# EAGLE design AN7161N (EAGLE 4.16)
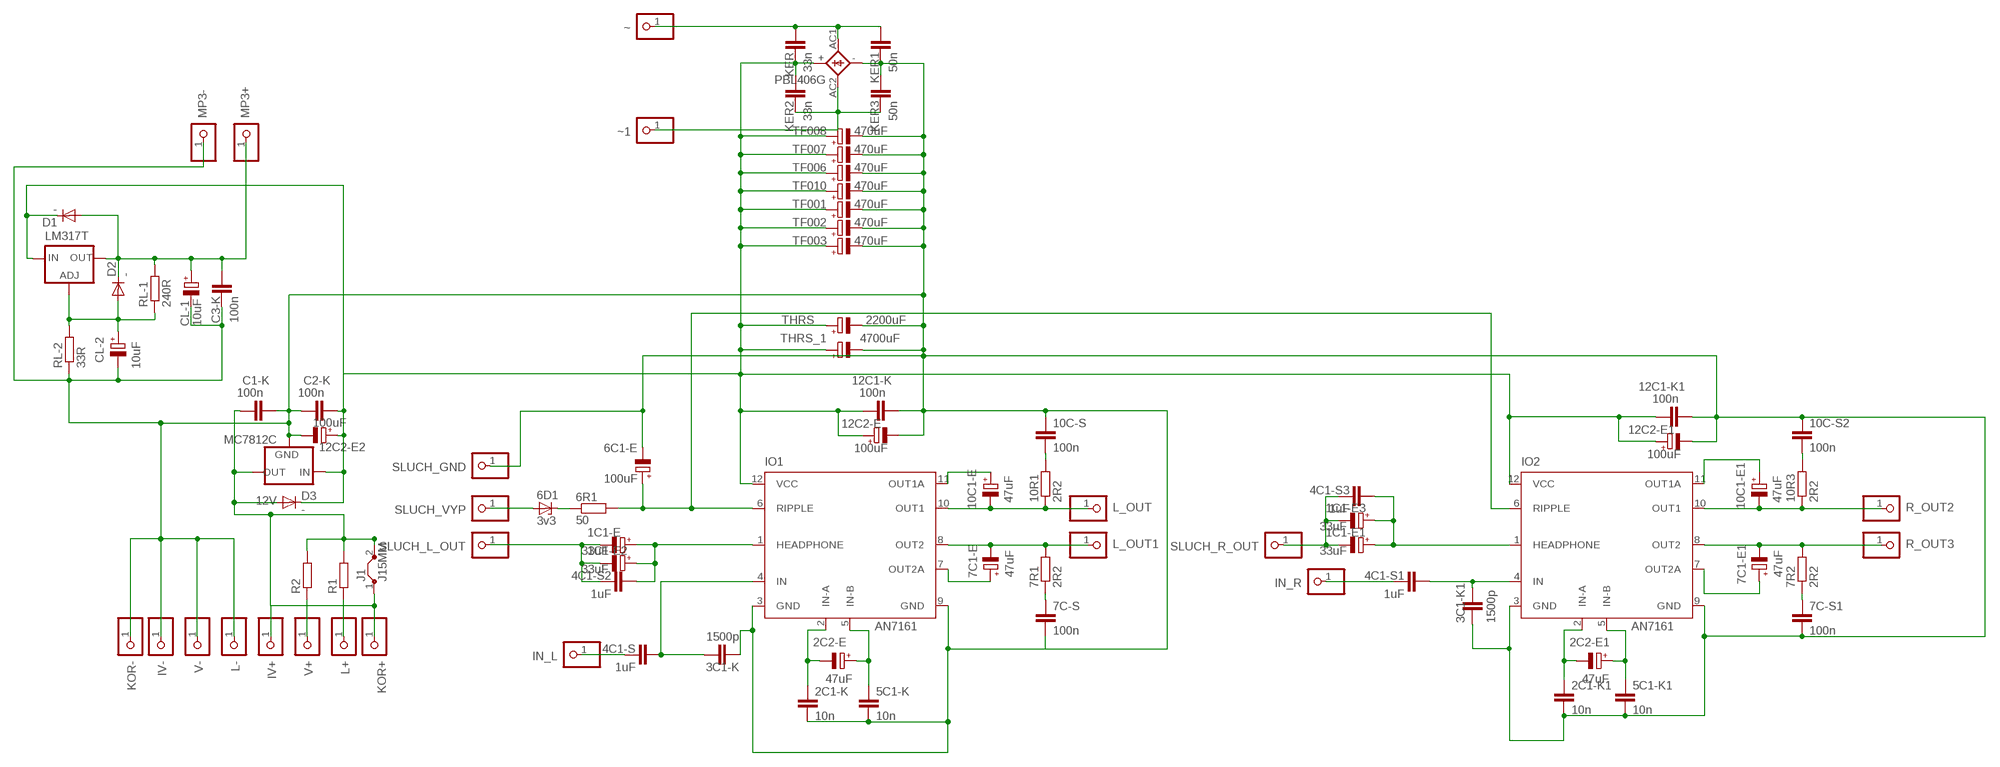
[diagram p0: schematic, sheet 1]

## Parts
1C1-E  33uF  CPOL-EUE5-6  [E5-6]
1C1-E1  33uF  CPOL-EUE5-6  [E5-6]
1C1-E2  33uF  CPOL-EUE5-6  [E5-6]
1C1-E3  33uF  CPOL-EUE5-6  [E5-6]
2C1-K  10n  C-EU050-024X044  [C050-024X044]
2C1-K1  10n  C-EU050-024X044  [C050-024X044]
2C2-E  47uF  CPOL-EUE5-6  [E5-6]
2C2-E1  47uF  CPOL-EUE5-6  [E5-6]
3C1-K  1500p  C-EU102-043X133  [C102-043X133]
3C1-K1  1500p  C-EU102-043X133  [C102-043X133]
4C1-S  1uF  C-EU225-087X268  [C225-087X268]
4C1-S1  1uF  C-EU225-087X268  [C225-087X268]
4C1-S2  1uF  C-EU225-087X268  [C225-087X268]
4C1-S3  1uF  C-EU225-087X268  [C225-087X268]
5C1-K  10n  C-EU050-024X044  [C050-024X044]
5C1-K1  10n  C-EU050-024X044  [C050-024X044]
6C1-E  100uF  CPOL-EUE5-10.5  [E5-10,5]
6D1  3v3  1N821  [DO35Z10]
6R1  50  R-EU_0207/12  [0207/12]
7C1-E  47uF  CPOL-EUE5-6  [E5-6]
7C1-E1  47uF  CPOL-EUE5-6  [E5-6]
7C-S  100n  CXXC15B8  [XC15B8]
7C-S1  100n  CXXC15B8  [XC15B8]
7R1  2R2  R-EU_0207/15  [0207/15]
7R2  2R2  R-EU_0207/15  [0207/15]
10C1-E  47uF  CPOL-EUE5-6  [E5-6]
10C1-E1  47uF  CPOL-EUE5-6  [E5-6]
10C-S  100n  CXXC15B8  [XC15B8]
10C-S2  100n  CXXC15B8  [XC15B8]
10R1  2R2  R-EU_0207/15  [0207/15]
10R3  2R2  R-EU_0207/15  [0207/15]
12C1-K  100n  C-EU050-024X044  [C050-024X044]
12C1-K1  100n  C-EU050-024X044  [C050-024X044]
12C2-E  100uF  CPOL-EUE5-8.5  [E5-8,5]
12C2-E1  100uF  CPOL-EUE5-8.5  [E5-8,5]
12C2-E2  100uF  CPOL-EUE5-8.5  [E5-8,5]
C1-K  100n  C-EU050-024X044  [C050-024X044]
C2-K  100n  C-EU050-024X044  [C050-024X044]
C3-K  100n  C-EU050-024X044  [C050-024X044]
CL-1  10uF  CPOL-EUE5-6  [E5-6]
CL-2  10uF  CPOL-EUE5-6  [E5-6]
D1  -  1N5060GP  [DO15-12]
D2  -  1N5060GP  [DO15-12]
D3  -  1N5060GP  [DO15-12]
IN_L  PINHD-1X1  [1X01]
IN_R  PINHD-1X1  [1X01]
IO1  AN7161  [SIP-12]
IO2  AN7161  [SIP-12]
IV+  PINHD-1X1  [1X01]
IV-  PINHD-1X1  [1X01]
J1  J15MM  [15]
KER  33n  C-EU050-024X044  [C050-024X044]
KER1  50n  C-EU050-024X044  [C050-024X044]
KER2  33n  C-EU050-024X044  [C050-024X044]
KER3  50n  C-EU050-024X044  [C050-024X044]
KOR+  PINHD-1X1  [1X01]
KOR-  PINHD-1X1  [1X01]
L+  PINHD-1X1  [1X01]
L-  PINHD-1X1  [1X01]
L_OUT  PINHD-1X1  [1X01]
L_OUT1  PINHD-1X1  [1X01]
LM317T  LM317TS  [317TS]
MC7812C  12V  78XXS  [78XXS]
MP3+  PINHD-1X1  [1X01]
MP3-  PINHD-1X1  [1X01]
PBL406G  KBL  [KBL]
R1  R-EU_0411/15  [0411/15]
R2  R-EU_0411/15  [0411/15]
R_OUT2  PINHD-1X1  [1X01]
R_OUT3  PINHD-1X1  [1X01]
RL-1  240R  R-EU_0207/12  [0207/12]
RL-2  33R  R-EU_0207/12  [0207/12]
SLUCH_GND  PINHD-1X1  [1X01]
SLUCH_L_OUT  PINHD-1X1  [1X01]
SLUCH_R_OUT  PINHD-1X1  [1X01]
SLUCH_VYP  PINHD-1X1  [1X01]
TF001  470uF  CPOL-EUE35-12AXIAL  [E35-12]
TF002  470uF  CPOL-EUE35-12AXIAL  [E35-12]
TF003  470uF  CPOL-EUE35-12AXIAL  [E35-12]
TF006  470uF  CPOL-EUE35-12AXIAL  [E35-12]
TF007  470uF  CPOL-EUE35-12AXIAL  [E35-12]
TF008  470uF  CPOL-EUE35-12AXIAL  [E35-12]
TF010  470uF  CPOL-EUE35-12AXIAL  [E35-12]
THRS  2200uF  CPOL-EUE7.5-18  [E7,5-18]
THRS_1  4700uF  CPOL-EUE7.5-18  [E7,5-18]
V+  PINHD-1X1  [1X01]
V-  PINHD-1X1  [1X01]
~  PINHD-1X1  [1X01]
~1  PINHD-1X1  [1X01]

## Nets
N$1: 2C1-K1.1 2C2-E1.- IO2.2(IN-A)
N$2: 1C1-E2.- 1C1-E.- 4C1-S2.1 SLUCH_L_OUT.1
N$4: 6D1.C 6R1.1
N$6: 2C1-K.1 2C2-E.- IO1.2(IN-A)
N$8: 4C1-S.1 IN_L.1
N$9: 10C1-E1.+ IO2.11(OUT1A)
N$11: 2C2-E.+ 5C1-K.1 IO1.5(IN-B)
N$12: 10C1-E.+ IO1.11(OUT1A)
N$14: 7C1-E.- 7R1.2 IO1.8(OUT2) L_OUT1.1
N$15: 7C1-E.+ IO1.7(OUT2A)
N$16: 7C-S.1 7R1.1
N$17: 10C-S.2 10R1.2
N$18: 7C1-E1.- 7R2.2 IO2.8(OUT2) R_OUT3.1
N$21: 7C-S1.1 7R2.1
N$23: 1C1-E1.- 1C1-E3.- 4C1-S3.1 SLUCH_R_OUT.1
N$27: 1C1-E2.+ 1C1-E.+ 4C1-S2.2 IO1.1(HEADPHONE)
N$28: 2C2-E1.+ 5C1-K1.1 IO2.5(IN-B)
N$30: 10C-S2.2 10R3.2
N$32: 7C1-E1.+ IO2.7(OUT2A)
N$33: KER1.2 KER.2 PBL406G.AC1(AC2) ~.1
N$34: C1-K.1 D3.A IV+.1 J1.1 J1.2 KOR+.1 MC7812C.OUT R1.2 R2.2
N$35: L+.1 R1.1
N$38: 3C1-K1.1 4C1-S1.2 IO2.4(IN)
N$41: 4C1-S1.1 IN_R.1
N$42: 10C1-E1.- 10R3.1 IO2.10(OUT1) R_OUT2.1
N$46: 1C1-E1.+ 1C1-E3.+ 4C1-S3.2 IO2.1(HEADPHONE)
N$51: 6C1-E.+ 6R1.2 IO1.6(RIPPLE) IO2.6(RIPPLE)
N$52: 10C1-E.- 10R1.1 IO1.10(OUT1) L_OUT.1
N$56: 3C1-K.1 4C1-S.2 IO1.4(IN)
N$57: R2.1 V+.1
N$58: 2C1-K1.2 2C1-K.2 3C1-K1.2 3C1-K.2 5C1-K1.2 5C1-K.2 6C1-E.- 7C-S1.2 7C-S.2 10C-S2.1 10C-S.1 12C1-K1.2 12C1-K.2 12C2-E1.- 12C2-E2.- 12C2-E.- C1-K.2 C2-K.1 C3-K.1 CL-1.- CL-2.- IO1.3(GND) IO1.9(GND) IO2.3(GND) IO2.9(GND) IV-.1 KER1.1 KER3.2 KOR-.1 L-.1 MC7812C.GND MP3-.1 PBL406G.- RL-2.1 SLUCH_GND.1 TF001.- TF002.- TF003.- TF006.- TF007.- TF008.- TF010.- THRS.- THRS_1.- V-.1
N$59: 6D1.A SLUCH_VYP.1
N$64: C3-K.2 CL-1.+ D1.A D2.C LM317T.2(OUT) MP3+.1 RL-1.2
N$69: KER2.1 KER3.1 PBL406G.AC2(AC1) ~1.1
N$72: 12C1-K1.1 12C1-K.1 12C2-E1.+ 12C2-E2.+ 12C2-E.+ C2-K.2 D1.C D3.C IO1.12(VCC) IO2.12(VCC) KER2.2 KER.1 LM317T.3(IN) MC7812C.IN PBL406G.+ TF001.+ TF002.+ TF003.+ TF006.+ TF007.+ TF008.+ TF010.+ THRS.+ THRS_1.+
N$73: CL-2.+ D2.A LM317T.1(ADJ) RL-1.1 RL-2.2

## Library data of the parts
1C1-E 1C1-E1-1C1-E3 2C2-E 2C2-E1 6C1-E 7C1-E 7C1-E1 10C1-E 10C1-E1 12C2-E 12C2-E1 12C2-E2 CL-1 CL-2 TF001-TF003 TF006-TF008 TF010 THRS THRS_1 = rcl:CPOL-EU: POLARIZED CAPACITOR, European symbol
2C1-K 2C1-K1 3C1-K 3C1-K1 4C1-S 4C1-S1-4C1-S3 5C1-K 5C1-K1 12C1-K 12C1-K1 C1-K C2-K C3-K KER KER1-KER3 = rcl:C-EU: CAPACITOR, European symbol
6D1 = diode:1N821: Reference DIODE
6R1 7R1 7R2 10R1 10R3 R1 R2 RL-1 RL-2 = rcl:R-EU_: RESISTOR, European symbol
7C-S 7C-S1 10C-S 10C-S2 = rcl:CX: X CAPACITOR
D1-D3 = diode:1N5060GP: DIODE
IN_L IN_R IV+ IV- KOR+ KOR- L+ L- L_OUT L_OUT1 MP3+ MP3- R_OUT2 R_OUT3 SLUCH_GND SLUCH_L_OUT SLUCH_R_OUT SLUCH_VYP V+ V- ~ ~1 = pinhead:PINHD-1X1: PIN HEADER
IO1 IO2 = linear:AN7161: BTL High Audio Power Amplifier AN7161NFP Source: http://www.steren.com.mx/diagramas/uploads/an7161.pdf
J1 = jumper:J: Bridge
LM317T = v-reg:LM317TS: VOLTAGE REGULATOR
MC7812C = v-reg:78XXS: VOLTAGE REGULATOR
PBL406G = rectifier:KBL: DIOTEC RECTIFIER

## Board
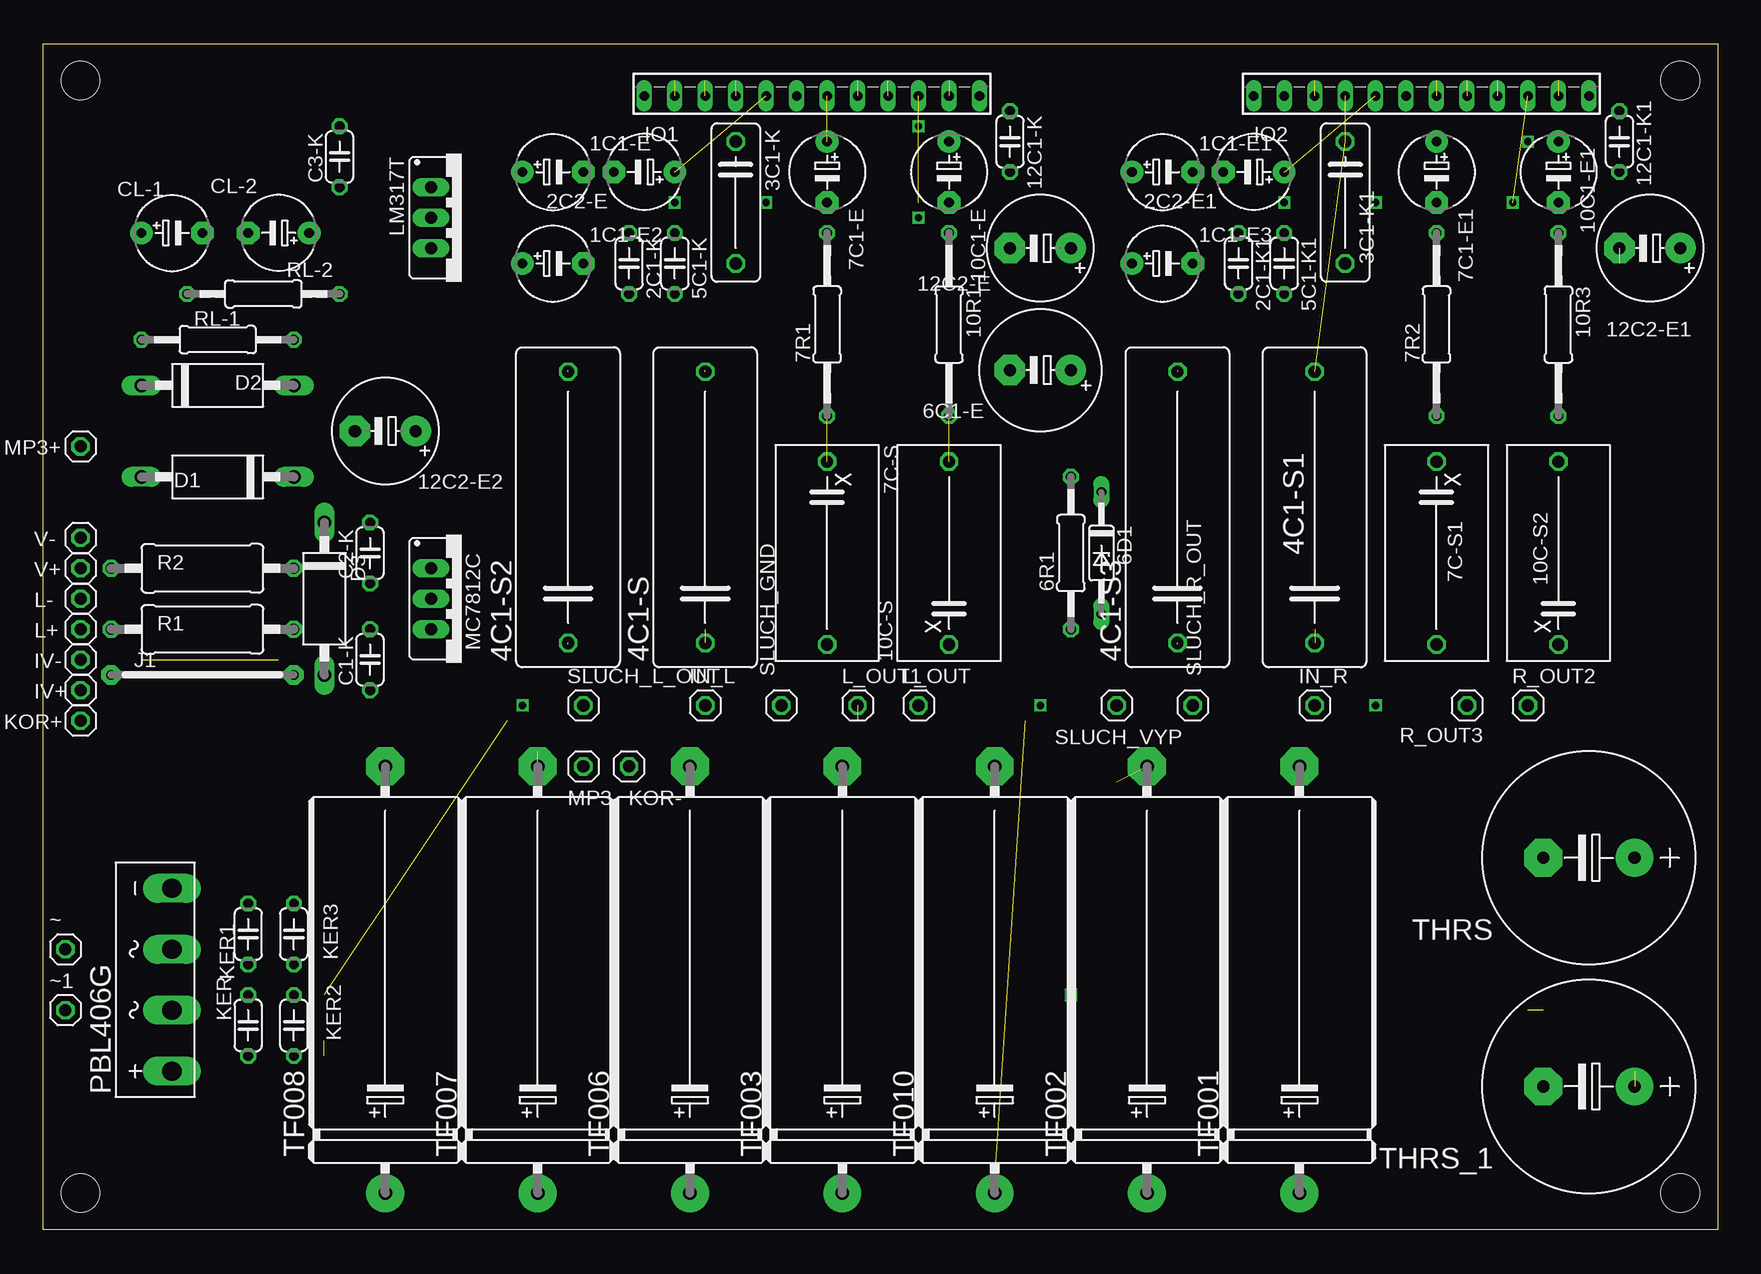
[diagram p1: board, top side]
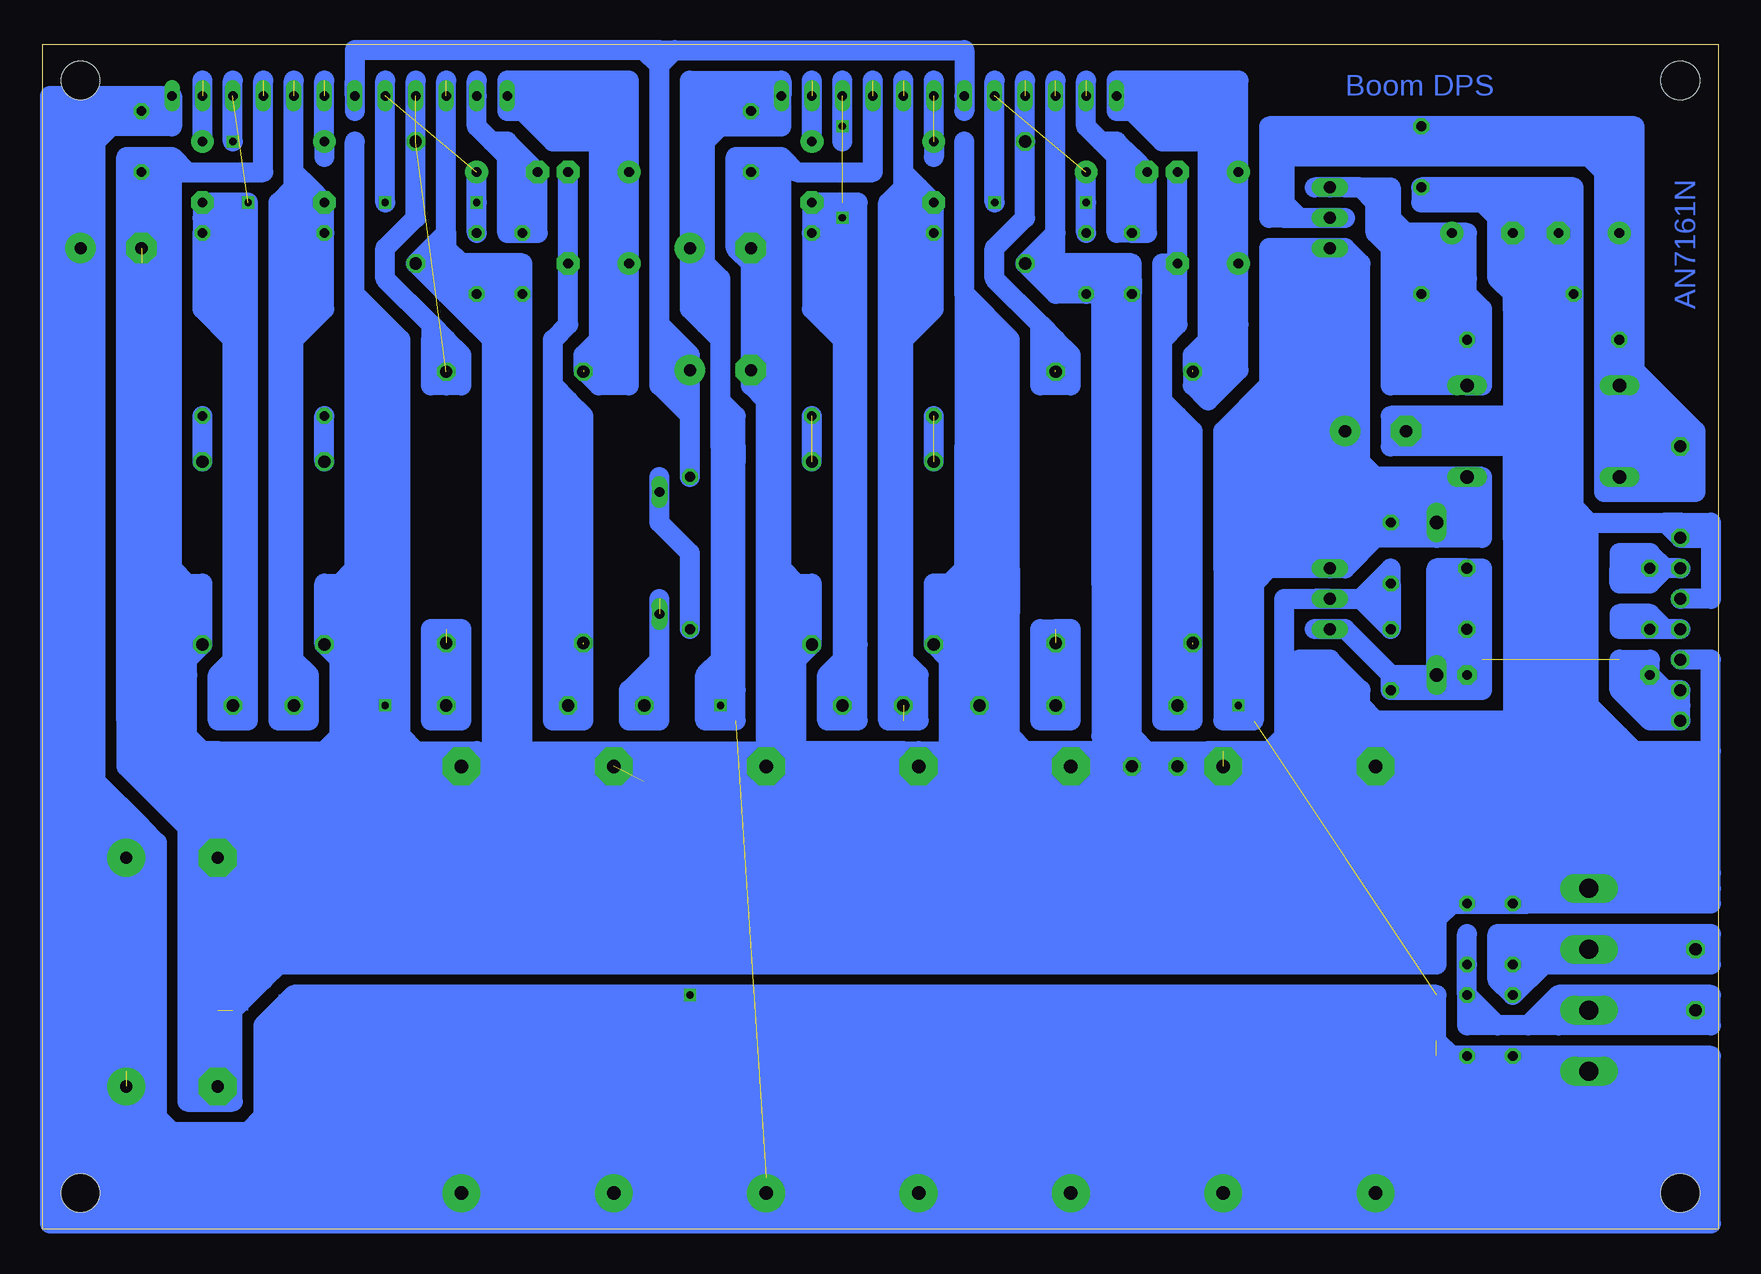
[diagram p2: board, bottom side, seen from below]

Size 139.68 x 98.73 mm. Coordinates in mm from the lower left corner, seen from the top.
Outline: 0,0 139.68,0 139.68,98.73 0,98.73 0,0
Copper layers (1*16): Top 0.035mm / dielectric 1.5mm / Bottom 0.035mm
Design rules "default": minimum track width 10mil, minimum drill 24mil, track to track 8mil, track to pad 8mil, pad to pad 8mil, via to via 8mil, smd to smd 8mil, copper to edge 40mil, drill to drill 8mil, minimum pad ring 10mil, minimum via ring 8mil, stop-mask expansion 4mil, vias tented up to drill 0mil, thermal gap 10mil
Holes 3.2 mm at 3.17,95.72 136.52,95.72 136.52,3.01 3.17,3.01

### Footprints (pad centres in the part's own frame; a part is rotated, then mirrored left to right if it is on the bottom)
E5-6 = drill 0.813 pad 1.905 round: + -2.54,0 | drill 0.813 pad 1.905 octagon: - 2.54,0
C050-024X044 = drill 0.813 octagon: 1 -2.54,0; 2 2.54,0
C102-043X133 = drill 1.016 octagon: 1 -5.08,0; 2 5.08,0
C225-087X268 = drill 1.016 octagon: 1 -11.303,0; 2 11.303,0
E5-10,5 = drill 1.016 pad 2.54 round: + -2.54,0 | drill 1.016 pad 2.54 octagon: - 2.54,0
DO35Z10 = drill 0.813 long: A 5.08,0; C -5.08,0
0207/12 = drill 0.813 octagon: 1 -6.35,0; 2 6.35,0
XC15B8 = drill 1.016 octagon: 1 -7.62,0; 2 7.62,0
0207/15 = drill 0.813 octagon: 1 -7.62,0; 2 7.62,0
E5-8,5 = drill 1.016 pad 2.54 round: + -2.54,0 | drill 1.016 pad 2.54 octagon: - 2.54,0
DO15-12 = drill 1.118 long: A 6.35,0; C -6.35,0
1X01 = drill 1.016 octagon: 1 0,0
SIP-12 = drill 0.8 pad 1.27 long: 1 -13.97,0; 2 -11.43,0; 3 -8.89,0; 4 -6.35,0; 5 -3.81,0; 6 -1.27,0; 7 1.27,0; 8 3.81,0; 9 6.35,0; 10 8.89,0; 11 11.43,0; 12 13.97,0
15 = drill 0.813 pad 1.6 octagon: 1 -7.62,0; 2 7.62,0
317TS = drill 1.016 long: 1 -2.54,-2.54; 2 0,-2.54; 3 2.54,-2.54
78XXS = drill 1.016 long: GND 0,-2.54; IN -2.54,-2.54; OUT 2.54,-2.54
KBL = drill 1.6 long: + -7.62,-1.27; - 7.62,-1.27; AC1 2.54,-1.27; AC2 -2.54,-1.27
0411/15 = drill 0.914 octagon: 1 -7.62,0; 2 7.62,0
E35-12 = drill 1.118 pad 3.15 round: + -17.78,0 | drill 1.118 pad 3.15 octagon: - 17.78,0
E7,5-18 = drill 1.016 pad 3.15 round: + -3.81,0 | drill 1.016 pad 3.15 octagon: - 3.81,0

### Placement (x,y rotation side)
1C1-E  42.54,88.1 0 top
1C1-E1  93.34,88.1 0 top
1C1-E2  42.54,80.48 0 top
1C1-E3  93.34,80.48 0 top
2C1-K  48.89,80.48 270 top
2C1-K1  99.69,80.48 270 top
2C2-E  50.16,88.1 180 top
2C2-E1  100.96,88.1 180 top
3C1-K  57.78,85.56 270 top
3C1-K1  108.58,85.56 270 top
4C1-S  55.24,60.16 90 top
4C1-S1  106.04,60.16 90 top
4C1-S2  43.81,60.16 90 top
4C1-S3  94.61,60.16 90 top
5C1-K  52.7,80.48 270 top
5C1-K1  103.5,80.48 270 top
6C1-E  83.18,71.59 180 top
6D1  88.26,56.35 270 top
6R1  85.72,56.35 90 top
7C1-E  65.4,88.1 270 top
7C1-E1  116.2,88.1 270 top
7C-S  65.4,56.35 270 top
7C-S1  116.2,56.35 270 top
7R1  65.4,75.4 90 top
7R2  116.2,75.4 90 top
10C1-E  75.56,88.1 270 top
10C1-E1  126.36,88.1 270 top
10C-S  75.56,56.35 90 top
10C-S2  126.36,56.35 90 top
10R1  75.56,75.4 270 top
10R3  126.36,75.4 270 top
12C1-K  80.64,90.64 270 top
12C1-K1  131.44,90.64 270 top
12C2-E  83.18,81.75 180 top
12C2-E1  133.98,81.75 180 top
12C2-E2  28.57,66.51 180 top
C1-K  27.3,47.46 90 top
C2-K  27.3,56.35 90 top
C3-K  24.76,89.37 90 top
CL-1  10.79,83.02 0 top
CL-2  19.68,83.02 180 top
D1  14.6,62.7 180 top
D2  14.6,70.32 0 top
D3  23.49,52.54 270 top
IN_L  55.24,43.65 0 top
IN_R  106.04,43.65 0 top
IO1  64.13,94.45 0 top
IO2  114.93,94.45 0 top
IV+  3.17,44.92 0 top
IV-  3.17,47.46 0 top
J1  13.33,46.19 0 top
KER  17.14,16.98 90 top
KER1  17.14,24.6 270 top
KER2  20.95,16.98 270 top
KER3  20.95,24.6 90 top
KOR+  3.17,42.38 0 top
KOR-  48.89,38.57 0 top
L+  3.17,50 0 top
L-  3.17,52.54 0 top
L_OUT  73.02,43.65 0 top
L_OUT1  67.94,43.65 0 top
LM317T  34.92,84.29 270 top
MC7812C  34.92,52.54 270 top
MP3+  3.17,65.24 0 top
MP3-  45.08,38.57 0 top
PBL406G  9.52,20.79 90 top
R1  13.33,50 0 top
R2  13.33,55.08 0 top
R_OUT2  123.82,43.65 0 top
R_OUT3  118.74,43.65 0 top
RL-1  14.6,74.13 180 top
RL-2  18.41,77.94 0 top
SLUCH_GND  61.59,43.65 0 top
SLUCH_L_OUT  45.08,43.65 0 top
SLUCH_R_OUT  95.88,43.65 0 top
SLUCH_VYP  89.53,43.65 0 top
TF001  104.77,20.79 90 top
TF002  92.07,20.79 90 top
TF003  66.67,20.79 90 top
TF006  53.97,20.79 90 top
TF007  41.27,20.79 90 top
TF008  28.57,20.79 90 top
TF010  79.37,20.79 90 top
THRS  128.9,30.95 180 top
THRS_1  128.9,11.9 180 top
V+  3.17,55.08 0 top
V-  3.17,57.62 0 top
~  1.9,23.33 0 top
~1  1.9,18.25 0 top

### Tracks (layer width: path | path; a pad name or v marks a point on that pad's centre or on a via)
N$1
  Bottom 1.676: 100.96,83.02 100.96,89.37 102.23,90.64 | 103.5,95.72 IO2.2 103.5,91.91 102.23,90.64 | 102.23,90.64 100.96,90.64 2C2-E1.- | 99.69,86.83 2C2-E1.- | 99.69,86.83 2C1-K1.1 100.96,83.02 | 99.69,86.83 99.69,88.1 | 2C2-E1.- 98.42,83.02 100.96,83.02
N$2  (1 unrouted)
  Bottom 1.676: 1C1-E2.- 1C1-E.- | 1C1-E2.- 45.08,75.4 46.35,74.13 | 46.35,53.81 46.35,69.05 | 46.35,69.05 46.35,74.13 | 46.35,51.27 46.35,53.81 | 43.81,48.73 46.35,51.27 | 43.81,44.92 43.81,48.73 | 43.81,44.92 SLUCH_L_OUT.1 45.08,48.73 46.35,50 46.35,51.27 | 46.35,51.27 46.35,42.38 43.81,42.38 43.81,44.92 | 43.81,48.73 43.81,50 | 43.81,50 43.81,51.27 45.08,52.54 | 46.35,53.81 45.08,52.54 | 46.35,53.81 46.35,52.54 45.08,51.27 | 1C1-E2.- 46.35,80.48 46.35,74.13 | 43.81,50 43.81,66.51 45.08,67.78 | 46.35,69.05 45.08,67.78 | 45.08,52.54 45.08,67.78
N$3
  Bottom 1.676: 66.67,76.67 66.67,81.75
N$4
  Bottom 1.676: 6R1.1 85.72,56.35 88.26,58.89 6D1.C 88.26,62.7
N$5
  Bottom 1.676: 133.98,29.68 133.98,32.22
N$6  (1 unrouted)
  Bottom 1.676: 52.7,95.72 52.7,91.91 51.43,90.64 | 50.16,90.64 51.43,90.64 | 2C2-E.- 48.89,89.37 | 48.89,89.37 50.16,90.64 | 48.89,86.83 2C2-E.- | 2C1-K.1 48.89,86.83 | 48.89,86.83 48.89,89.37 | 2C1-K.1 50.16,83.02 50.16,89.37 | 50.16,89.37 50.16,90.64 | 50.16,89.37 51.43,90.64 | 2C2-E.- 47.62,83.02 2C1-K.1
N$8  (1 unrouted)
  Bottom 1.676: 55.24,50 56.51,50 56.51,47.46 | 55.24,50 53.97,50 53.97,47.46 | 55.24,50 55.24,46.19 | 55.24,46.19 IN_L.1 | 53.97,44.92 53.97,42.38 56.51,42.38 56.51,44.92 | 53.97,44.92 56.51,44.92 | 53.97,47.46 56.51,47.46 | 53.97,44.92 53.97,47.46 | 55.24,46.19 56.51,46.19 56.51,47.46 | 56.51,44.92 56.51,47.46
N$9  (1 unrouted)
  Bottom 1.676: 10C1-E1.+ 126.36,95.72
N$10  (via drill 0.6)
  Bottom 1.676: v60.32,85.56 60.32,95.72
N$11  (via drill 0.6)  (1 unrouted)
  Bottom 1.676: 5C1-K.1 v52.7,85.56 2C2-E.+
N$12  (1 unrouted)
  Bottom 1.676: 10C1-E.+ 75.56,95.72
N$14  (2 unrouted)
  Bottom 1.676: 67.94,42.38 69.21,42.38 69.21,85.56 67.94,86.83 | 67.94,42.38 66.67,42.38 66.67,46.19 67.94,47.46 | 67.94,42.38 67.94,47.46 | 67.94,47.46 67.94,74.13 | 67.94,74.13 67.94,80.48 | 67.94,80.48 67.94,81.75 66.67,83.02 | 7R1.2 66.67,83.02 | 7R1.2 7C1-E.- 66.67,86.83 | 67.94,88.1 67.94,95.72 | 67.94,86.83 67.94,88.1 | 67.94,80.48 67.94,86.83 | 67.94,88.1 66.67,86.83 | 66.67,83.02 66.67,86.83 | 7R1.2 65.4,76.67 67.94,74.13
N$15  (1 unrouted)
N$16  (1 unrouted)
N$17  (1 unrouted)
N$18  (1 unrouted)
  Bottom 1.676: 118.74,88.1 118.74,95.72 | 117.47,86.83 7C1-E1.- 7R2.2 | 118.74,88.1 117.47,86.83 | 7R2.2 118.74,80.48 118.74,74.13 | 118.74,47.46 R_OUT3.1 120.01,43.65 | 118.74,47.46 118.74,74.13 | 120.01,43.65 120.01,85.56 118.74,86.83 118.74,88.1 | 117.47,86.83 117.47,83.02 118.74,81.75 118.74,85.56 | 7R2.2 116.2,76.67 118.74,74.13 | 118.74,74.13 118.74,79.21 117.47,80.48 117.47,76.67 | 120.01,43.65 120.01,42.38 117.47,42.38 117.47,46.19 118.74,47.46
N$21
  Bottom 1.676: 7C-S1.1 7R2.1
N$22
  Bottom 1.676: 93.34,91.91 93.34,93.18
N$23  (1 unrouted)
  Bottom 1.676: 1C1-E1.- 1C1-E3.- 95.88,75.4 97.15,74.13 97.15,70.32 | 97.15,53.81 97.15,70.32 | 97.15,50 97.15,53.81 | 97.15,50 97.15,42.38 94.61,42.38 94.61,43.65 | 94.61,43.65 SLUCH_R_OUT.1 95.88,47.46 | 94.61,48.73 95.88,47.46 | 94.61,43.65 94.61,48.73 | 94.61,48.73 94.61,51.27 | 97.15,53.81 94.61,51.27 | 95.88,51.27 95.88,47.46 | 94.61,51.27 94.61,67.78 95.88,69.05 | 95.88,69.05 97.15,70.32 | 95.88,51.27 95.88,69.05 | 97.15,50 95.88,51.27
N$26
  Bottom 1.676: 67.94,37.3 67.94,36.03
N$27  (1 unrouted)
  Bottom 1.676: IO1.1 50.16,95.72 40,95.72 1C1-E.+ | IO1.1 50.16,93.18 45.08,93.18 | 43.81,91.91 45.08,93.18 | 42.54,90.64 43.81,91.91 | 1C1-E.+ 42.54,90.64 | 1C1-E.+ 1C1-E2.+ 40,75.4 | 40,75.4 42.54,72.86 | 43.81,71.59 42.54,72.86 | IO1.1 41.27,94.45 | 43.81,93.18 45.08,93.18 | 43.81,93.18 41.27,93.18 41.27,90.64 | 41.27,90.64 43.81,93.18 | 42.54,72.86 42.54,74.13 | 42.54,74.13 41.27,75.4 41.27,90.64 | 42.54,90.64 41.27,90.64 | 42.54,74.13 42.54,90.64 | 40,71.59 40,75.4 | 40,71.59 43.81,71.59 | 43.81,71.59 42.54,71.59 41.27,72.86 | 42.54,74.13 43.81,72.86 43.81,71.59 | 42.54,90.64 45.08,90.64 | 42.54,90.64 46.35,90.64 IO1.1 | 43.81,91.91 46.35,91.91 | 40,71.59 42.54,69.05 43.81,70.32 43.81,71.59 | 40,71.59 41.27,71.59 42.54,70.32
N$28  (via drill 0.6)  (1 unrouted)
  Bottom 1.676: 5C1-K1.1 v103.5,85.56 2C2-E1.+
N$29  (via drill 0.6)
  other vias: 85.72,19.52
N$30
  Bottom 1.676: 10C-S2.2 10R3.2
N$31
  Bottom 1.676: 114.93,48.73 114.93,52.54
N$32  (1 unrouted)
  Bottom 1.676: 116.2,95.72 7C1-E1.+ 116.2,89.37
N$33
  Bottom 1.676: PBL406G.AC1 ~.1 | PBL406G.AC1 12.06,23.33 | KER.2 KER1.2 | 13.33,22.06 0.63,22.06 0.63,24.6 13.33,24.6 | 13.33,22.06 13.33,23.33 | 13.33,23.33 13.33,24.6 | 15.87,22.06 KER1.2 | 14.6,22.06 15.87,22.06 | 13.33,22.06 14.6,22.06 | 14.6,22.06 KER.2 | 13.33,24.6 14.6,24.6 | 14.6,24.6 KER1.2 | 13.33,23.33 14.6,23.33 15.87,22.06 | KER.2 18.41,20.79 18.41,24.6 15.87,24.6 | 14.6,24.6 15.87,24.6 | 15.87,24.6 17.14,23.33 | 13.33,23.33 PBL406G.AC1
N$34  (1 unrouted)
  Bottom 1.676: 3.17,43.65 KOR+.1 4.44,42.38 | 33.65,50 MC7812C.OUT 31.11,50 27.3,46.19 | 27.3,46.19 C1-K.1 19.68,44.92 19.68,46.19 | R2.2 R1.2 | J1.2 R2.2 | J1.2 22.22,46.19 | D3.A 22.22,46.19 | 27.3,46.19 D3.A | D3.A 23.49,55.08 R2.2 | J1.2 20.95,47.46 | 19.68,47.46 20.95,47.46 | R2.2 20.95,47.46 | R2.2 19.68,55.08 19.68,47.46 | 19.68,46.19 19.68,47.46 | 19.68,46.19 J1.2 | D3.A 23.49,53.81 22.22,55.08 22.22,46.19 | 4.44,42.38 6.98,44.92 8.25,44.92 | 8.25,44.92 8.25,47.46 5.71,47.46 J1.1 | J1.1 6.98,46.19 5.71,44.92 | 5.71,44.92 J1.1 | J1.1 4.44,44.92 IV+.1 3.17,43.65 | 3.17,43.65 4.44,43.65 5.71,44.92 | 4.44,42.38 5.71,42.38 8.25,44.92
N$35
  Bottom 1.676: L+.1 4.44,50 | 4.44,50 R1.1 8.25,50 8.25,51.27 5.71,51.27 4.44,50
N$36
  Bottom 1.676: 60.32,72.86 60.32,74.13 61.59,75.4 61.59,66.51 60.32,66.51 60.32,71.59
N$38  (2 unrouted)
N$39  (via drill 0.6)
  Bottom 1.676: 73.02,90.64 v73.02,91.91 73.02,95.72
N$40  (via drill 0.6)
  Bottom 1.676: v123.82,90.64 123.82,95.72
N$41  (1 unrouted)
  Bottom 1.676: 106.04,50 104.77,50 104.77,42.38 107.31,42.38 107.31,50 106.04,50 | 106.04,50 IN_R.1
N$42  (via drill 0.6)  (1 unrouted)
  Bottom 1.676: 126.36,84.29 10R3.1 | 126.36,84.29 10C1-E1.- v122.55,85.56 122.55,43.65 | 125.09,81.75 123.82,80.48 123.82,74.13 | 10R3.1 125.09,81.75 | 123.82,47.46 R_OUT2.1 122.55,43.65 | 123.82,47.46 123.82,74.13 | 126.36,84.29 123.82,84.29 | 126.36,84.29 123.82,81.75 123.82,83.02 | 123.82,74.13 126.36,76.67 10R3.1 | 125.09,81.75 125.09,76.67 | 123.82,47.46 125.09,46.19 125.09,42.38 122.55,42.38 122.55,43.65
N$46  (1 unrouted)
  Bottom 1.676: IO2.1 100.96,93.18 95.88,93.18 93.34,90.64 | 1C1-E1.+ 93.34,90.64 | 1C1-E1.+ 1C1-E3.+ 90.8,71.59 | 90.8,71.59 94.61,71.59 | 94.61,71.59 94.61,72.86 93.34,74.13 93.34,90.64 | 1C1-E1.+ 90.8,95.72 100.96,95.72 IO2.1 | IO2.1 95.88,94.45 | 95.88,94.45 92.07,94.45 92.07,72.86 93.34,72.86 | 95.88,94.45 94.61,93.18 | 93.34,90.64 97.15,90.64 IO2.1 | IO2.1 98.42,94.45 95.88,91.91 97.15,91.91 | 94.61,71.59 93.34,70.32 90.8,70.32 90.8,71.59
N$47
  Bottom 1.676: 75.56,63.97 75.56,67.78
N$48
  Bottom 1.676: 76.83,48.73 76.83,52.54
N$50
  Bottom 1.676: 84.45,93.18 84.45,91.91
N$51
  Bottom 1.676: IO2.6 113.66,93.18 | IO2.6 113.66,95.72 | 62.86,93.18 IO1.6 62.86,98.26 86.99,98.26 | 6C1-E.+ 86.99,70.32 | 88.26,98.26 86.99,98.26 | 88.26,98.26 89.53,98.26 | 89.53,98.26 113.66,98.26 IO2.6 | 88.26,75.4 88.26,96.99 | 88.26,96.99 88.26,98.26 | 88.26,75.4 88.26,74.13 6C1-E.+ | 88.26,70.32 88.26,75.4 | 88.26,70.32 86.99,71.59 | 85.72,70.32 6C1-E.+ | 85.72,67.78 85.72,70.32 | 6R1.2 85.72,67.78 | 85.72,67.78 88.26,70.32 | 85.72,70.32 85.72,72.86 88.26,75.4 | 88.26,96.99 86.99,98.26 | 88.26,96.99 89.53,98.26
N$52  (via drill 0.6)  (1 unrouted)
  Bottom 1.676: 74.29,75.4 74.29,83.02 | 10C1-E.- 10R1.1 75.56,76.67 74.29,75.4 | 73.02,74.13 L_OUT.1 | 73.02,81.75 73.02,74.13 | 73.02,81.75 73.02,83.02 10C1-E.- | 73.02,74.13 74.29,75.4 | 73.02,85.56 71.75,85.56 71.75,48.73 | 73.02,85.56 10C1-E.- | 71.75,48.73 71.75,42.38 74.29,42.38 74.29,46.19 71.75,48.73 | 73.02,85.56 v73.02,84.29 73.02,81.75
N$53
  Bottom 1.676: 13.33,85.56 17.14,85.56
N$54
  Bottom 1.676: 65.4,63.97 65.4,67.78
N$55
  Bottom 1.676: 65.4,89.37 65.4,90.64 65.4,94.45 65.4,95.72
N$56  (2 unrouted)
  Bottom 1.676: 53.97,72.86 56.51,72.86 | 53.97,72.86 53.97,70.32 56.51,70.32 56.51,72.86 | 57.78,95.72 3C1-K.1 57.78,84.29 60.32,81.75 60.32,79.21 56.51,75.4 | 55.24,74.13 56.51,75.4 | 55.24,74.13 55.24,71.59 56.51,72.86 | 56.51,72.86 56.51,75.4 | 53.97,72.86 55.24,74.13
N$57
  Bottom 1.676: V+.1 4.44,55.08 | 4.44,55.08 R2.1 8.25,55.08 | 4.44,55.08 5.71,53.81 8.25,53.81 8.25,55.08 | 4.44,55.08 5.71,56.35 8.25,56.35 8.25,55.08
N$58  (via drill 0.6)  (8 unrouted)
  Bottom 1.676: 12.06,60.16 12.06,43.65 13.33,43.65 13.33,62.7 14.6,62.7 | 70.48,95.72 70.48,88.1 76.83,88.1 78.1,89.37 81.91,89.37 81.91,81.75 | 132.71,44.92 132.71,88.1 | 130.17,85.56 130.17,52.54 128.9,51.27 | 121.28,95.72 121.28,88.1 127.63,88.1 | 128.9,88.1 127.63,88.1 | 128.9,88.1 130.17,88.1 | 127.63,50 10C-S2.1 | 127.63,50 132.71,55.08 | 106.04,83.02 106.04,95.72 | 3C1-K1.2 106.04,83.02 | 100.96,77.94 2C1-K1.2 | 100.96,77.94 102.23,77.94 | 2C1-K1.2 99.69,80.48 103.5,80.48 | 3C1-K1.2 103.5,80.48 | 103.5,80.48 104.77,80.48 106.04,81.75 106.04,83.02 | 99.69,66.51 2C1-K1.2 | 108.58,39.84 103.5,39.84 | 114.93,39.84 108.58,39.84 | 116.2,39.84 114.93,39.84 | 125.09,39.84 126.36,39.84 | 125.09,39.84 116.2,39.84 | 126.36,39.84 127.63,39.84 127.63,41.11 | 127.63,41.11 127.63,46.19 | 127.63,46.19 127.63,47.46 10C-S2.1 | 114.93,41.11 114.93,47.46 7C-S1.2 116.2,53.81 114.93,53.81 | 114.93,39.84 114.93,41.11 | 111.12,53.81 114.93,53.81 | 111.12,53.81 v111.12,43.65 111.12,41.11 113.66,41.11 113.66,52.54 112.39,52.54 112.39,42.38 | 127.63,46.19 127.63,50 | 127.63,41.11 128.9,41.11 | 128.9,41.11 131.44,41.11 | 131.44,52.54 131.44,80.48 | 131.44,80.48 131.44,85.56 | 131.44,52.54 130.17,51.27 | 128.9,41.11 128.9,51.27 | 128.9,41.11 128.9,48.73 131.44,51.27 131.44,52.54 | 130.17,42.38 130.17,50 132.71,52.54 132.71,44.92 | 132.71,42.38 131.44,42.38 | 131.44,42.38 131.44,50 | 108.58,39.84 109.85,41.11 109.85,53.81 | 116.2,39.84 114.93,41.11 | 126.36,39.84 127.63,41.11 | 109.85,53.81 111.12,53.81 | 100.96,65.24 99.69,66.51 | 109.85,56.35 111.12,56.35 | 112.39,56.35 113.66,56.35 113.66,55.08 | 67.94,39.84 76.83,39.84 | 76.83,39.84 78.1,39.84 | 79.37,39.84 78.1,39.84
  Bottom 1.676: 99.69,39.84 79.37,39.84 | TF003.- 67.94,39.84 | TF002.- TF001.- 123.82,38.57 125.09,39.84 | 89.53,37.3 88.26,36.03 | TF010.- TF003.- | 103.5,79.21 3C1-K1.2 | 103.5,79.21 100.96,79.21 | 102.23,77.94 5C1-K1.2 | 5C1-K1.2 106.04,77.94 | 102.23,77.94 103.5,79.21 | 127.63,88.1 128.9,89.37 | 12C1-K1.2 128.9,89.37 | 12C1-K1.2 131.44,86.83 | 131.44,85.56 131.44,86.83 | 131.44,85.56 130.17,86.83 | 128.9,51.27 128.9,53.81 | 128.9,53.81 128.9,55.08 | 128.9,55.08 128.9,88.1 | 131.44,80.48 131.44,86.83 | 132.71,89.37 12C1-K1.2 | 66.67,23.33 67.94,23.33 | TF003.- 66.67,24.6 | 132.71,42.38 132.71,44.92 | 131.44,41.11 132.71,42.38 | 131.44,41.11 131.44,42.38 | 67.94,25.87 67.94,34.76 | 71.75,30.95 71.75,29.68 | TF002.- 100.96,38.57 100.96,39.84 | 10C-S2.1 126.36,53.81 127.63,53.81 | 128.9,53.81 127.63,53.81 | 128.9,53.81 127.63,52.54 | 127.63,52.54 127.63,51.27 | 127.63,53.81 127.63,52.54 | 128.9,55.08 127.63,53.81 | 76.83,39.84 76.83,47.46 10C-S.1 75.56,53.81 76.83,53.81 78.1,55.08 | 78.1,55.08 78.1,88.1 79.37,88.1 | 79.37,88.1 12C1-K.2 12C2-E.- | 79.37,39.84 79.37,69.05 | 79.37,69.05 79.37,80.48 | 79.37,83.02 79.37,88.1 | 78.1,39.84 78.1,55.08 | 80.64,72.86 80.64,80.48 | 12C2-E.- 80.64,80.48 | 79.37,83.02 12C2-E.- | 79.37,80.48 79.37,83.02 | 79.37,80.48 12C2-E.- | 12C2-E.- 81.91,81.75 | 80.64,72.86 6C1-E.- | 64.13,47.46 7C-S.2 65.4,53.81 64.13,53.81 | 64.13,47.46 64.13,39.84 66.67,39.84 | 67.94,39.84 66.67,39.84 | TF003.- 66.67,39.84 | 109.85,53.81 109.85,55.08 | 109.85,55.08 109.85,56.35 | 109.85,55.08 113.66,55.08 | 114.93,53.81 113.66,55.08 | 50.16,77.94 2C1-K.2 48.89,79.21 | 51.43,77.94 50.16,77.94 | 100.96,65.24 100.96,76.67 | 100.96,76.67 100.96,77.94 | 100.96,76.67 102.23,77.94
  Bottom 1.676: KOR-.1 50.16,39.84 | TF003.- 61.59,38.57 | 61.59,38.57 57.78,38.57 | 62.86,55.08 62.86,65.24 | 64.13,53.81 62.86,55.08 | 64.13,47.46 64.13,53.81 | 62.86,55.08 62.86,39.84 61.59,39.84 SLUCH_GND.1 | SLUCH_GND.1 61.59,63.97 60.32,63.97 60.32,55.08 | 60.32,50 60.32,39.84 59.05,39.84 59.05,41.11 | 59.05,41.11 59.05,55.08 | 50.16,61.43 50.16,63.97 | 50.16,39.84 51.43,39.84 | 51.43,39.84 57.78,39.84 59.05,41.11 | 59.05,37.3 65.4,37.3 65.4,36.03 | 65.4,36.03 65.4,32.22 60.32,32.22 60.32,36.03 64.13,36.03 | 64.13,36.03 65.4,36.03 | 48.89,41.11 48.89,53.81 | 48.89,39.84 48.89,41.11 | 48.89,53.81 51.43,53.81 | 51.43,53.81 51.43,41.11 50.16,41.11 50.16,42.38 | 50.16,42.38 50.16,52.54 | 48.89,53.81 48.89,57.62 | 48.89,57.62 48.89,58.89 51.43,58.89 | 51.43,53.81 51.43,55.08 | 51.43,53.81 51.43,57.62 | 51.43,57.62 50.16,57.62 | 50.16,57.62 50.16,55.08 | 59.05,56.35 59.05,57.62 | 62.86,65.24 59.05,65.24 59.05,63.97 | 51.43,57.62 51.43,77.94 | 50.16,57.62 50.16,61.43 | 50.16,61.43 50.16,77.94 | 48.89,57.62 48.89,61.43 | 48.89,61.43 48.89,79.21 | 48.89,79.21 48.89,80.48 56.51,80.48 | 48.89,61.43 50.16,61.43 | 59.05,56.35 59.05,63.97 | 59.05,55.08 59.05,51.27 60.32,50 | 60.32,50 60.32,55.08 | 59.05,56.35 60.32,55.08 | 59.05,55.08 59.05,56.35 | 55.24,83.02 55.24,95.72 | 55.24,83.02 3C1-K.2 55.24,77.94 5C1-K.2 51.43,77.94 | 55.24,83.02 55.24,79.21 48.89,79.21 | 62.86,77.94 62.86,90.64 | 62.86,77.94 62.86,65.24 | 62.86,77.94 59.05,74.13 59.05,63.97 | 113.66,55.08 113.66,77.94 | 113.66,77.94 113.66,90.64 | 106.04,77.94 3C1-K1.2 | 103.5,79.21 106.04,79.21 | 102.23,75.4 102.23,77.94 | 102.23,74.13 102.23,75.4 | 102.23,74.13 102.23,39.84 100.96,39.84 | 102.23,75.4 103.5,75.4
  Bottom 1.676: 103.5,75.4 106.04,77.94 | 102.23,74.13 103.5,75.4 | 103.5,75.4 5C1-K1.2 | 109.85,56.35 109.85,74.13 113.66,77.94 | 112.39,56.35 112.39,75.4 | 111.12,56.35 112.39,56.35 | 111.12,56.35 111.12,74.13 | 80.64,80.48 81.91,81.75 | 79.37,69.05 80.64,70.32 80.64,72.86 | 0.63,28.41 0.63,29.68 | 0.63,28.41 PBL406G.- | PBL406G.- 12.06,28.41 | 0.63,28.41 0.63,27.14 13.33,27.14 | 13.33,27.14 13.33,28.41 | 13.33,28.41 13.33,29.68 | 0.63,29.68 13.33,29.68 | 66.67,23.33 36.19,23.33 36.19,41.11 | 42.54,39.84 41.27,39.84 | 48.89,39.84 47.62,39.84 | 47.62,39.84 42.54,39.84 | MC7812C.GND 33.65,52.54 | 29.84,52.54 C2-K.1 | 29.84,52.54 C1-K.2 C2-K.1 | MC7812C.GND 29.84,52.54 | 0.63,29.68 0.63,39.84 | 0.63,39.84 0.63,47.46 IV-.1 | 0.63,57.62 0.63,52.54 L-.1 | V-.1 0.63,57.62 | MC7812C.GND 36.19,52.54 36.19,41.11 | 14.6,79.21 15.87,79.21 | 15.87,79.21 17.14,79.21 | CL-1.- CL-2.- | 12.06,84.29 CL-1.- | RL-2.1 12.06,84.29 | 17.14,79.21 17.14,84.29 | 17.14,84.29 13.33,84.29 CL-1.- | CL-2.- 17.14,84.29 | CL-2.- 17.14,80.48 15.87,80.48 | 15.87,80.48 14.6,80.48 14.6,81.75 | 14.6,81.75 14.6,84.29 15.87,84.29 15.87,80.48 | 15.87,57.62 14.6,57.62 | C2-K.1 27.3,51.27 | C2-K.1 28.57,52.54 | 15.87,79.21 15.87,76.67 | 15.87,76.67 15.87,58.89 | 15.87,58.89 14.6,58.89 | 15.87,58.89 15.87,57.62 | 37.46,39.84 42.54,39.84 | 8.25,39.84 37.46,39.84 | 13.33,28.41 KER1.1 | KER1.1 15.87,27.14 | 8.25,39.84 10.79,42.38 13.33,42.38 | 15.87,42.38 13.33,42.38 | 15.87,42.38 17.14,42.38 | 17.14,42.38 28.57,42.38 | 28.57,41.11 28.57,42.38 | 17.14,41.11 28.57,41.11 | 17.14,41.11 8.25,41.11 | 15.87,76.67 15.87,77.94 17.14,79.21 | KER1.1 KER3.2 22.22,27.14 | 22.22,27.14 23.49,27.14 23.49,25.87 | 23.49,25.87 23.49,22.06 121.28,22.06
  Bottom 1.676: 13.33,28.41 PBL406G.- | 13.33,29.68 23.49,29.68 23.49,28.41 14.6,28.41 | 13.33,27.14 22.22,27.14 | 22.22,27.14 23.49,25.87 | 15.87,43.65 15.87,42.38 | 15.87,57.62 15.87,43.65 | RL-2.1 14.6,79.21 | 19.68,86.83 C3-K.1 24.76,85.56 19.68,85.56 | 19.68,86.83 18.41,85.56 | 17.14,84.29 18.41,85.56 | 12.06,84.29 12.06,86.83 19.68,86.83 | 18.41,85.56 19.68,85.56 | 0.63,57.62 0.63,58.89 3.17,58.89 | 12.06,63.97 RL-2.1 | 3.17,58.89 V-.1 | 15.87,43.65 17.14,42.38 | 34.92,47.46 32.38,47.46 29.84,44.92 29.84,43.65 | 29.84,43.65 29.84,41.11 | 28.57,42.38 29.84,43.65 | V-.1 4.44,58.89 3.17,58.89 | 17.14,79.21 18.41,79.21 | 18.41,79.21 18.41,84.29 19.68,85.56 | 61.59,38.57 SLUCH_GND.1 | 50.16,39.84 50.16,42.38 | 99.69,39.84 99.69,66.51 | 100.96,39.84 99.69,39.84 | 100.96,39.84 100.96,65.24 | 37.46,39.84 36.19,41.11 | 48.89,41.11 47.62,39.84 | 132.71,89.37 128.9,89.37 | 132.71,88.1 132.71,89.37 | 132.71,88.1 12C1-K1.2 | 8.25,39.84 8.25,37.3 | 13.33,42.38 14.6,43.65 | 17.14,57.62 17.14,41.11 | 15.87,58.89 17.14,57.62 | 12.06,63.97 13.33,63.97 14.6,62.7 | 14.6,81.75 13.33,81.75 13.33,65.24 | 17.14,57.62 17.14,65.24 | 17.14,65.24 17.14,66.51 | 17.14,76.67 17.14,67.78 | 17.14,67.78 17.14,66.51 | 17.14,79.21 17.14,76.67 | 17.14,76.67 17.14,77.94 18.41,79.21 | 0.63,39.84 6.98,39.84 10.79,43.65 10.79,58.89 | 10.79,58.89 12.06,60.16 | 12.06,60.16 12.06,63.97 | 14.6,62.7 14.6,44.92 | 17.14,66.51 12C2-E2.- | 17.14,65.24 27.3,65.24 27.3,67.78 17.14,67.78 | 29.84,52.54 27.3,55.08 C2-K.1 | 14.6,79.21 14.6,63.97 | 10.79,58.89 3.17,58.89 | 28.57,41.11 TF008.- MP3-.1 | MP3-.1 KOR-.1 | KOR-.1 48.89,39.84 | 48.89,39.84 51.43,39.84 | 51.43,39.84 53.97,39.84 TF006.- TF003.- | TF003.- 64.13,38.57 64.13,36.03
  Bottom 1.676: 64.13,36.03 79.37,36.03 TF010.- | TF002.- TF010.- | 114.93,29.68 122.55,22.06 121.28,22.06 | 132.71,42.38 132.71,38.57 | 132.71,38.57 125.09,38.57 125.09,32.22 | 125.09,32.22 THRS.- | 125.09,32.22 126.36,30.95 126.36,34.76 | 121.28,22.06 121.28,20.79 | TF002.- TF010.- | TF010.- TF003.- | TF003.- arc180 66.67,24.6 | 67.94,25.87 73.02,30.95 74.29,30.95 | 66.67,24.6 66.67,23.33 | 66.67,24.6 67.94,25.87 | 67.94,25.87 67.94,27.14 71.75,30.95 | 74.29,30.95 71.75,30.95 | 74.29,30.95 84.45,30.95 TF002.- | MP3-.1 KOR-.1 | KOR-.1 TF002.- | 126.36,39.84 131.44,39.84 | 132.71,38.57 127.63,33.49 127.63,23.33 127.63,10.63 123.82,10.63 123.82,18.25 117.47,24.6 | 126.36,34.76 126.36,37.3 128.9,37.3 | 128.9,37.3 130.17,37.3 | 126.36,34.76 128.9,37.3 | 126.36,34.76 127.63,34.76 128.9,36.03 | 122.55,20.79 125.09,18.25 THRS_1.-
N$59  (1 unrouted)
  Bottom 1.676: 90.8,44.92 89.53,44.92 | 90.8,44.92 90.8,42.38 88.26,42.38 88.26,44.92 | 88.26,47.46 88.26,52.54 | 88.26,44.92 88.26,47.46 | 88.26,44.92 SLUCH_VYP.1 | 88.26,47.46 90.8,44.92
N$60
  Bottom 1.676: 64.13,34.76 64.13,33.49 61.59,33.49 61.59,34.76 64.13,34.76
N$61
  Bottom 1.676: 107.31,71.59 107.31,70.32 106.04,70.32 | 104.77,71.59 104.77,72.86 | 104.77,72.86 106.04,74.13 | 106.04,74.13 107.31,75.4 | 106.04,72.86 106.04,74.13 | 106.04,70.32 106.04,71.59 | 106.04,70.32 104.77,70.32 104.77,71.59 | 104.77,71.59 106.04,71.59 | 106.04,71.59 107.31,71.59 | 107.31,71.59 107.31,72.86 | 104.77,72.86 106.04,72.86 | 107.31,72.86 106.04,72.86 | 108.58,95.72 108.58,84.29 111.12,81.75 111.12,79.21 107.31,75.4 | 107.31,75.4 107.31,74.13 | 107.31,72.86 107.31,74.13 | 106.04,71.59 107.31,72.86 | 106.04,71.59 106.04,72.86 | 106.04,72.86 107.31,74.13
N$62  (via drill 0.6)
  Bottom 1.676: v111.12,85.56 111.12,95.72
N$64
  Bottom 1.676: 36.19,84.29 34.92,84.29 | 34.92,84.29 LM317T.2 31.11,84.29 | 36.19,88.1 36.19,89.37 10.79,89.37 | 36.19,88.1 36.19,85.56 | 36.19,85.56 36.19,84.29 | 10.79,89.37 8.25,89.37 | 8.25,89.37 CL-1.+ RL-1.2 D2.C D1.A MP3+.1 | 8.25,89.37 6.98,89.37 | 6.98,71.59 6.98,89.37 | 6.98,71.59 6.98,70.32 | 6.98,70.32 6.98,69.05 | 9.52,88.1 10.79,89.37 | 6.98,89.37 6.98,90.64 | 6.98,90.64 36.19,90.64 | 36.19,88.1 36.19,90.64 | 6.98,90.64 6.98,91.91 C3-K.2 36.19,91.91 | 36.19,90.64 36.19,91.91 | 36.19,84.29 37.46,84.29 37.46,91.91 36.19,91.91 | 36.19,85.56 34.92,84.29 | 1.9,65.24 MP3+.1 | 1.9,63.97 1.9,65.24 | 9.52,63.97 1.9,63.97 | 9.52,63.97 9.52,88.1 | 9.52,88.1 8.25,89.37 | 6.98,70.32 6.98,66.51 4.44,66.51 | 1.9,66.51 4.44,66.51 | 1.9,65.24 1.9,66.51 | 1.9,66.51 6.98,71.59 | 4.44,66.51 4.44,67.78 5.71,69.05 5.71,67.78 | 9.52,63.97 9.52,62.7 1.9,62.7 | 1.9,62.7 1.9,63.97 | MP3+.1 6.98,65.24 | 1.9,62.7 1.9,61.43 9.52,61.43 9.52,63.97
N$67
  Bottom 1.676: 126.36,11.9 126.36,18.25
N$68
  Bottom 1.676: 1.9,1.74 137.79,1.74
N$69
  Bottom 1.676: 13.33,16.98 0.63,16.98 0.63,19.52 13.33,19.52 | 13.33,16.98 13.33,19.52 | ~1.1 PBL406G.AC2 12.06,18.25 13.33,19.52 | 13.33,16.98 15.87,16.98 | 15.87,16.98 18.41,16.98 | 18.41,16.98 KER2.1 | KER2.1 KER3.1 | 13.33,19.52 15.87,16.98 | 18.41,16.98 20.95,16.98 KER2.1 | KER2.1 20.95,24.6
N$70
  Bottom 1.676: 22.22,81.75 24.76,81.75
N$72  (via drill 0.6)  (4 unrouted)
  Bottom 1.676: 120.01,16.98 120.01,4.28 132.71,4.28 THRS_1.+ | 135.25,37.3 135.25,90.64 133.98,91.91 | 135.25,34.76 135.25,37.3 | 135.25,34.76 135.25,27.14 | 135.25,27.14 135.25,18.25 | 128.9,93.18 128.9,91.91 133.98,91.91 | 128.9,93.18 IO2.12 136.52,94.45 | 136.52,94.45 137.79,94.45 137.79,81.75 | IO1.12 78.1,95.72 85.72,95.72 | 78.1,93.18 78.1,91.91 83.18,91.91 84.45,90.64 84.45,80.48 | 78.1,93.18 IO1.12 | 93.34,3.01 TF002.+ TF010.+ | 136.52,83.02 12C2-E1.+ | 137.79,81.75 137.79,34.76 | 137.79,34.76 137.79,18.25 | 137.79,81.75 136.52,83.02 | 136.52,83.02 136.52,16.98 | 84.45,80.48 84.45,77.94 | 84.45,77.94 85.72,77.94 | 85.72,77.94 12C2-E.+ | 12C2-E.+ 85.72,84.29 | 84.45,75.4 84.45,77.94 | 83.18,74.13 84.45,75.4 | 83.18,65.24 83.18,70.32 | 83.18,70.32 83.18,74.13 | 81.91,65.24 83.18,65.24 | 81.91,65.24 81.91,63.97 83.18,65.24 | 83.18,74.13 83.18,79.21 84.45,80.48 | 85.72,77.94 85.72,76.67 84.45,75.4 | IO1.12 85.72,94.45 | 85.72,95.72 12C1-K.1 | 81.91,44.92 81.91,65.24 | 81.91,44.92 81.91,42.38 83.18,42.38 | 81.91,44.92 v83.18,43.65 | 83.18,42.38 v83.18,43.65 | 83.18,70.32 83.18,69.05 81.91,67.78 81.91,65.24 | 83.18,65.24 83.18,47.46 | v83.18,43.65 83.18,47.46 | 83.18,42.38 84.45,42.38 84.45,46.19 83.18,47.46 | 128.9,93.18 12C1-K1.1 136.52,93.18 | TF010.+ TF003.+ | TF008.+ 1.9,3.01 | TF007.+ TF008.+ | TF006.+ TF007.+ | TF003.+ TF006.+ | 31.11,81.75 LM317T.3 37.46,81.75 37.46,70.32 | MC7812C.IN 37.46,55.08 | 37.46,55.08 38.73,55.08 | 40,55.08 41.27,55.08 | 41.27,55.08 41.27,42.38 40,42.38 | 40,42.38 38.73,42.38 38.73,53.81 | 38.73,55.08 38.73,53.81 | 38.73,55.08 40,55.08 | 40,55.08 v40,43.65 40,42.38 | TF010.+ TF003.+ | 34.92,60.16 38.73,56.35 | 37.46,70.32 41.27,66.51 41.27,55.08
  Bottom 1.676: 37.46,70.32 37.46,60.16 | 78.1,93.18 12C1-K.1 | 12C1-K.1 85.72,93.18 85.72,95.72 | 12C2-E.+ 85.72,95.72 | 133.98,91.91 136.52,91.91 136.52,84.29 | 34.92,57.62 34.92,58.89 31.11,55.08 | 34.92,57.62 34.92,56.35 | 34.92,56.35 37.46,56.35 36.19,57.62 | 34.92,56.35 33.65,56.35 33.65,62.7 | 33.65,62.7 33.65,65.24 | 34.92,57.62 34.92,60.16 | 34.92,60.16 34.92,61.43 40,56.35 | 33.65,66.51 33.65,67.78 | 33.65,65.24 33.65,66.51 | 33.65,66.51 32.38,66.51 | 33.65,65.24 32.38,66.51 | 37.46,55.08 38.73,53.81 | D1.C 19.68,62.7 19.68,57.62 23.49,57.62 | D1.C 28.57,62.7 | 28.57,62.7 29.84,62.7 | 29.84,62.7 32.38,62.7 | 32.38,62.7 33.65,62.7 | 23.49,57.62 D3.C | D3.C C2-K.2 28.57,58.89 MC7812C.IN | 31.11,55.08 MC7812C.IN | 23.49,57.62 28.57,57.62 31.11,55.08 | D1.C 20.95,58.89 22.22,58.89 | D3.C 22.22,58.89 | D3.C 23.49,60.16 | 23.49,60.16 23.49,61.43 | 23.49,61.43 22.22,61.43 22.22,58.89 | 23.49,61.43 32.38,61.43 32.38,57.62 31.11,57.62 31.11,60.16 29.84,60.16 | 23.49,60.16 29.84,60.16 | 29.84,60.16 29.84,58.89 | 12C2-E2.+ 32.38,66.51 | 31.11,81.75 12C2-E2.+ | 12C2-E2.+ 31.11,63.97 | 29.84,62.7 29.84,63.97 | 29.84,63.97 29.84,80.48 31.11,81.75 | 28.57,62.7 29.84,63.97 | 32.38,62.7 32.38,80.48 33.65,80.48 33.65,67.78 | 34.92,63.97 34.92,66.51 | 34.92,63.97 34.92,62.7 | 34.92,66.51 34.92,80.48 | 34.92,66.51 33.65,67.78 | 34.92,60.16 34.92,63.97 | TF007.+ TF008.+ | TF006.+ TF007.+ | TF003.+ TF006.+ | TF010.+ TF003.+ | TF010.+ 79.37,4.28 93.34,4.28 93.34,3.01 | 93.34,3.01 TF001.+ 133.98,3.01 | 133.98,3.01 137.79,3.01 137.79,4.28 | TF007.+ TF008.+ | 135.25,34.76 THRS.+ | 137.79,34.76 135.25,34.76 | 133.98,28.41 132.71,29.68 132.71,28.41 | 135.25,27.14 133.98,28.41 | 132.71,28.41 132.71,13.17
  Bottom 1.676: 133.98,28.41 133.98,20.79 | 133.98,20.79 133.98,3.01 | 133.98,3.01 135.25,3.01 137.79,5.55 137.79,16.98 135.25,16.98 135.25,4.28 136.52,5.55 136.52,15.71 | 135.25,34.76 133.98,34.76 132.71,33.49 THRS.+ | THRS.+ 132.71,28.41 | 135.25,37.3 131.44,33.49 | 131.44,33.49 131.44,24.6 | 131.44,33.49 130.17,32.22 130.17,24.6 | 133.98,20.79 130.17,24.6 | 136.52,94.45 139.06,94.45 139.06,0.47 0.63,0.47 0.63,14.44 KER.1 KER2.2 22.22,14.44 23.49,15.71 23.49,19.52 118.74,19.52 121.28,16.98 121.28,9.36 122.55,8.09 128.9,8.09 130.17,9.36 130.17,24.6 | PBL406G.+ 1.9,13.17 | PBL406G.+ 23.49,13.17 23.49,14.44 | 10.79,4.28 PBL406G.+
N$73
  Bottom 1.676: 20.95,79.21 20.95,83.02 CL-2.+ 26.03,83.02 27.3,84.29 | 20.95,79.21 23.49,79.21 RL-2.2 RL-1.1 | 20.95,79.21 20.95,77.94 19.68,76.67 19.68,75.4 | RL-1.1 20.95,76.67 | 19.68,75.4 RL-1.1 | RL-1.1 22.22,74.13 | 22.22,74.13 23.49,75.4 | 19.68,75.4 19.68,70.32 D2.A 27.3,70.32 27.3,81.75 28.57,83.02 28.57,85.56 29.84,86.83 31.11,86.83 | 31.11,86.83 LM317T.1 33.65,86.83 | 31.11,86.83 27.3,86.83 27.3,84.29 | 27.3,84.29 27.3,83.02 26.03,81.75 26.03,71.59 20.95,71.59 20.95,72.86 24.76,72.86 24.76,80.48 22.22,80.48 22.22,74.13 | 22.22,74.13 23.49,74.13 23.49,77.94
N$74
  Bottom 1.676: 131.44,22.06 131.44,5.55 121.28,5.55 121.28,8.09 122.55,6.82 130.17,6.82 130.17,8.09
N$75
  Bottom 1.676: 34.92,46.19 34.92,41.11 31.11,41.11 31.11,43.65 33.65,46.19 32.38,46.19 31.11,44.92
N$76
  Bottom 1.676: 33.65,44.92 33.65,42.38 32.38,42.38 32.38,43.65
N$79
  Bottom 1.676: 36.19,61.43 36.19,80.48
N$80
  Bottom 1.676: 38.73,58.89 38.73,67.78
N$81
  Bottom 1.676: 40,57.62 40,66.51
(copper drawn outside any net)
  shapes: Bottom area x7

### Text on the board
Bottom: Boom DPS | AN7161N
